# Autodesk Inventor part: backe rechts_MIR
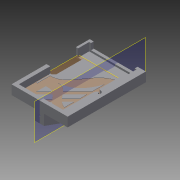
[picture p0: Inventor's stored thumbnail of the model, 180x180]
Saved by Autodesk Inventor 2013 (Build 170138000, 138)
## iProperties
Created: 2012-11
Part Number: backe rechts_MIR
Material: Allgemein
Document SubType Name: Modeling
Designer: otto
Density: 1 g/cm^3
Mass: 3948.56 g
Surface Area: 4189.4 cm^2
Volume: 3948.56 cm^3
d0: 1,000 oE
d1: 10,000 mm
d2: 10,000 mm
d3: 10,000 mm
d4: 60,000 mm
d5: 1,500 mm
d6: 0,00 grd
d7: 15,000 mm
d8: 0,00 grd
d9: 250,000 mm
d10: 49,000 mm
d11: 125,000 mm
d12: 0,00 grd
d13: 30,000 mm
d15: 200,000 mm
d16: 0,00 grd
d29: 5,000 mm
d31: 196,750 mm
d32: 0,00 grd
d33: 16,500 mm
d34: 0,00 grd
d35: 60,000 mm
d36: 0,00 grd
d37: 15,000 mm
d38: 0,00 grd
d0_1: 10,000 mm
Author: otto
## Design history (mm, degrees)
derived "backe rechts.ipt"
  sketch "Skizze2"
    geometry: L1 (-62.842, 56.837)-(16.083, -22.088) reference; L2 (-62.842, 122.085)-(-62.842, 56.837) reference; L3 (3.226, -37.408)-(-62.842, 28.66) reference; L4 (-62.842, 28.66)-(-62.842, -13.09) reference; L5 (-62.842, -13.09)-(-15.644, -60.289) reference; L6 (-29.786, -74.431)-(-62.842, -41.374) reference; L7 (-62.842, -41.374)-(-62.842, -94.979) reference; L8 (14.414, -124.654)-(-5.433, -104.806) reference; L9 (-31.938, -124.654)-(14.414, -124.654) reference; L10 (7.843, -89.829)-(42.668, -124.654) reference; L11 (42.668, -124.654)-(87.677, -124.654) reference; L12 (87.677, -123.652)-(29.098, -65.073) reference; L13 (-103.52, -137.92)-(134.48, -137.92) reference; L14 (-103.52, -137.92)-(-103.52, 384.83) reference; L15 (134.48, 384.83)-(-103.52, 384.83) reference; L16 (134.48, -137.92)-(134.48, 384.83) reference; L17 (44.725, -52.895)-(87.677, -95.847) reference; L18 (87.677, -124.654)-(87.677, -123.652) reference; L19 (87.677, -95.847)-(87.677, -45.538) reference; L20 (125.48, -53.223)-(125.48, 16.777) reference; L21 (130.48, 16.777)-(130.48, -53.223) reference; L22 (130.48, -53.223)-(125.48, -53.223) reference; L23 (-99.52, 106.777)-(-99.52, 176.777) reference; L24 (-94.52, 176.777)-(-94.52, 106.777) reference; L25 (-94.52, 106.777)-(-99.52, 106.777) reference; L26 (-94.52, 176.777)-(-99.52, 176.777) reference; L27 (130.48, 16.777)-(125.48, 16.777) reference; L28 (135.48, 16.777)-(130.48, 16.777) reference; L29 (-99.52, 176.777)-(-104.52, 176.777) reference; L30 (135.48, 16.777)-(135.48, 26.777) reference; L31 (135.48, 26.777)-(125.48, 26.777) reference; L32 (-104.52, 176.777)-(-104.52, 186.777) reference; L33 (-104.52, 186.777)-(-94.52, 186.777) reference; L34 (-94.52, 186.777)-(-34.52, 186.777) reference; L35 (-34.52, 186.777)-(125.48, 26.777) reference; 2 further points
  sketch "Skizze3"
    geometry: L1 (135.48, 26.777)-(135.48, 16.777) reference; L2 (125.48, 26.777)-(135.48, 26.777) reference; L3 (-34.52, 186.777)-(125.48, 26.777) reference; L4 (-104.52, 186.777)-(-34.52, 186.777) reference; L5 (-104.52, 176.777)-(-104.52, 186.777) reference; L6 (-104.52, 176.777)-(-104.52, 59.1) reference; L7 (-104.52, 16.777)-(-104.52, -143.223) reference; L8 (-104.52, -143.223)-(135.48, -143.223) reference; L9 (135.48, -143.223)-(135.48, 16.777) reference; A1 r 10.381 centre (-114.837, 60.254) between (-115.363, 49.886) and (-104.52, 59.1) reference; A2 r 14.76 centre (-116.112, 35.145) between (-115.363, 49.886) and (-129.525, 28.983) reference; A3 r 4.23 centre (-125.681, 30.748) between (-129.525, 28.983) and (-121.507, 31.429) reference; A4 r 5.422 centre (-116.156, 32.301) between (-112.095, 35.893) and (-121.507, 31.429) reference; A5 r 30.238 centre (-134.744, 15.859) between (-104.52, 16.777) and (-112.095, 35.893) reference; 1 further point
  workplane "Arbeitsebene1"
sketch "Skizze4"
  geometry: L1 (305, 0)-(0, 0) reference; L2 (147.5, -22.276)-(147.5, 447.57) reference; L3 (157.5, -22.276)-(157.5, 447.57) reference; L4 (128, 250)-(177, 250); L5 (177, 250)-(177, 0); L6 (177, 0)-(128, 0); L7 (128, 0)-(128, 250); L8 (152.5, 228.252)-(152.5, 197.369); 1 further point
  constraints: 14 end point, 3 parallel, 2 vertical, 1 collinear, 1 horizontal, 1 perpendicular, 5 other
  dimensions: "d9" = 250 distance between parallel lines of L1 L4; "d10" = 49 distance between parallel lines of L7 L5
extrude "Extrusion1" join sketch "Skizze4" distance "d11" = 125; taper "d12" = 0 deg
sketch "Skizze5"
  geometry: L1 (-16.365, -23.986)-(-187.376, 445.86) reference; L2 (-45.244, -32.357)-(-184.933, 351.435); L3 (-184.933, 351.435)-(-190.607, -42.949); L4 (-190.607, -42.949)-(-45.244, -32.357); 1 further point
  constraints: 8 end point, 1 parallel, 3 other
  dimensions: "d13" = 30 distance between parallel lines of L1 L2
extrude "Extrusion2" cut sketch "Skizze5" distance "d15" = 200; taper "d16" = 0 deg
workplane "Arbeitsebene2"
sketch "Skizze6"
  geometry: L1 (-10.563, -9.934)-(-181.573, 459.912) reference; L2 (-19.96, -13.354)-(-190.97, 456.492) reference; L3 (-140.058, 331.229)-(-0.172, -53.104); L4 (-139.653, 330.118)-(-134.966, 331.86); L5 (-16.052, -9.472)-(-11.354, -7.762); 1 further point
  constraints: 10 end point, 4 point on line, 1 parallel, 1 perpendicular, 6 other
  dimensions: "d29" = 5 distance between parallel lines of L2 L3
revolve "Umdrehung2" stored, may be unused: angle "d30" = 90 deg
sketch "Skizze11"
  geometry: L1 (-169, -34)-(69, -34) reference; L2 (69, -34)-(69, 34) reference; L3 (69, 34)-(-169, 34) reference; L4 (-169, 34)-(-169, -34) reference; L5 (-169, 34)-(69, 34); L6 (69, 34)-(69, 0); L7 (69, 0)-(-169, 0); L8 (-169, 0)-(-169, 34); 1 further point
  constraints: 8 end point, 2 parallel, 1 horizontal, 1 midpoint, 1 perpendicular
extrude "Extrusion7" cut sketch "Skizze11" distance "d31" = 196.75; taper "d32" = 0 deg
sketch "Skizze12"
  geometry: L1 (128, 0)-(128, 250) reference; L2 (128, 250)-(177, 250) reference; L3 (177, 250)-(177, 0) reference; L4 (305, 0)-(177, 0) reference; L5 (305, 190)-(305, 0) reference; L6 (275, 190)-(305, 190) reference; L7 (115, 350)-(275, 190) reference; L8 (0, 350)-(115, 350) reference; L9 (0, 0)-(0, 350) reference; L10 (128, 0)-(0, 0) reference; L11 (264, 350)-(35, 350) reference; L12 (264, 350)-(264, 201) reference; L13 (115, 350)-(264, 201); 1 further point
  constraints: 2 end point, 1 collinear
extrude "Extrusion8" join sketch "Skizze12" distance "d33" = 16.5; taper "d34" = 0 deg
sketch "Skizze13"
  geometry: L1 (-293, -44)-(-293, 44) reference; L2 (-293, 44)-(-35, 44) reference; L3 (-35, 44)-(-35, -44) reference; L4 (-305, 50.5)-(-305, 0) reference; L5 (-275, 50.5)-(-305, 50.5) reference; L6 (-264, 50.5)-(0, 50.5) reference; L7 (-264, 50.5)-(-275, 50.5) reference; L8 (0, 50.5)-(0, 0) reference; L9 (-305, 0)-(-293, 0); L10 (-35, 0)-(0, 0); 1 further point
  constraints: 4 end point, 2 midpoint, 1 collinear
extrude "Extrusion9" join sketch "Skizze13" distance "d35" = 60; taper "d36" = 0 deg
sketch "Skizze14"
  geometry: L1 (-293, 0)-(-293, 44) reference; L2 (-293, 44)-(-35, 44) reference; L3 (-35, 44)-(-35, 0) reference; L4 (-35, 0)-(0, 0) reference; L5 (0, 0)-(0, 50.5) reference; L6 (0, 50.5)-(-305, 50.5) reference; L7 (-305, 50.5)-(-305, 0) reference; L8 (-305, 0)-(-293, 0) reference; L9 (-283, -34)-(-283, 34) reference; L10 (-283, 34)-(-45, 34) reference; L11 (-45, 34)-(-45, -34) reference; L12 (-293, 0)-(-283, 0); L13 (-45, 0)-(-35, 0); 1 further point
  constraints: 4 end point, 2 midpoint, 1 collinear
extrude "Extrusion10" join sketch "Skizze14" distance "d37" = 15; taper "d38" = 0 deg
feature "Volumenkörper1::backe rechts.ipt" dims "d0" = 10
tag "Bezeichnung1"
node "Referenz8"
node "Referenz9"
node "Referenz10"
node "Referenz11"
node "Referenz12"
node "Referenz13"
node "Referenz14"
node "Referenz15"
node "Referenz16"
node "Volumenkörper1"
other parameters: "d0_1" = 10, "d1" = 10, "d2" = 10, "d3" = 10, "d4" = 60, "d5" = 1.5, "d6" = 0, "d7" = 15, "d8" = 0
